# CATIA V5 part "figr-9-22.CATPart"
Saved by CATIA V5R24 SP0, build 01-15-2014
Part number: Part3
Bounding box of the stored display mesh (mm): x -112 to 0, y -101.683 to 104.654, z -80.304 to 44.557
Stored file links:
  D:\KAVITA\CATIA V5-6R2014 Project_ Kavita\CATIA V5-6R2014_partfiles\Partfiles\c09_catia_v5-6r2014_prt\figr-9-22.CATPart
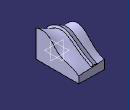
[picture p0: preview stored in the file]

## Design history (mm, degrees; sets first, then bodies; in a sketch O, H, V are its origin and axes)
Set1
  Plane1: type Offset, RefPlane yz-plane, Offset -112
  Plane2: type Offset, RefPlane yz-plane, Offset -63
  Plane3: type Normal, Curve Sketch4, RefPoint vertex of Sketch4
Body1 (main body)
  Sketch1 on yz-plane, origin (0, 0, 0), H (0, 1, 0), V (0, 0, 1)
    spline S1 through (-92.6897, 40.1119) (-30, 30) (10, -10) (60, -30) (97.3103, -50.3041)
    line L1 (97.3103, -50.3041) -> (97.3103, -80.3041)
    line L2 (97.3103, -80.3041) -> (-92.6897, -80.3041)
    line L3 (-92.6897, -80.3041) -> (-92.6897, 40.1119)
    point P3 (-92.6897, 40.1119)
    point P4 (97.3103, -50.3041)
    point P5 (-92.6897, 40.1119)
    point P6 (97.3103, -50.3041)
    vertical: L1 V, L3 V
    horizontal: L2 H
    coincidence: P5 P3, P6 P4
  Sketch2 on Plane1, origin (-112, 0, 0), H (0, 1, 0), V (0, 0, 1)
    spline S1 through (-90, -30) (-70, 10) (-20, 40) (40, 0) (100, -40)
    line L1 (100, -40) -> (100, -80)
    line L2 (100, -80) -> (-90, -80)
    line L3 (-90, -80) -> (-90, -30)
    point P3 (-90, -30)
    point P4 (100, -40)
    point P5 (40, 0)
    point P6 (-90, -30)
    point P7 (100, -40)
    coincidence: P5 H, P6 P3, P7 P4
    vertical: L1 V, L3 V
    horizontal: L2 H
  Loft1: Sections (Sketch1; Sketch2)
  Sketch3 on Plane3, origin (0, -40.1726, -44.9298), H (1, 0, 0), V (0, -0.7455, 0.6665)
    point P1 (-63, 68.4187)
    line L1 (-63, 68.4187) -> (-75.2117, 62.4925)
    line L2 (-75.2117, 62.4925) -> (-79.6266, 71.5898)
    line L3 (-79.6266, 71.5898) -> (-57.1205, 82.5119)
    line L4 (-57.1205, 82.5119) -> (-52.7056, 73.4145)
    point P5 (-52.7056, 73.4145)
    line L5 (-52.7056, 73.4145) -> (-63, 68.4187)
    reference projected point E1 (-63, 68.4187) from vertex of Sketch4
    perpendicularity: L2 L1
    parallelism: L3 L1, L4 L2, L5 L1
    coincidence: P5 L1, P1 E1
  Sketch4 on Plane2, origin (-63, 0, 0), H (0, 1, 0), V (0, 0, 1)
    intersected curve E1 from face of Loft1
  Rib1: profile Sketch3, centre curve Sketch4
